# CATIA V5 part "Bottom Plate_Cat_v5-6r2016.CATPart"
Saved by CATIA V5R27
Part number: Bottom Plate
Bounding box of the stored display mesh (mm): x -125 to 125, y 0 to 150, z 0 to 30
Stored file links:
  E:\_Deepak\2017_Deepak\CATIA\Resources\Tutorial Files\Tutorials\c12_catia_v5_6r2015_tut\c12tut2\Bottom Plate_Cat_v5-6r2016.CATPart
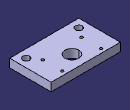
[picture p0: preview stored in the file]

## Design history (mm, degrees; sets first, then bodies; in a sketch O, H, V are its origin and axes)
Body1 (main body)
  Sketch1 on xy-plane, origin (0, 0, 0), H (1, 0, 0), V (0, 1, 0)
    point P1 (-125, 0)
    line L1 (-125, 0) -> (125, 0)
    line L2 (125, 0) -> (125, 150)
    line L3 (125, 150) -> (-125, 150)
    line L4 (-125, 150) -> (-125, 0)
    circle A1 centre (0, 100) radius 25
    point P5 (0, 100)
    circle A2 centre (95, 30) radius 12.5
    point P6 (95, 30)
    circle A3 centre (-95, 30) radius 12.5
    circle A4 centre (-70, 135) radius 5
    point P8 (-70, 135)
    construction line L5 (-25, 100) -> (25, 100)
    point P9 (-25, 100)
    point P10 (25, 100)
    construction line L6 (0, 125) -> (0, 75)
    point P11 (0, 125)
    point P12 (0, 75)
    circle A5 centre (-70, 65) radius 5
    circle A6 centre (70, 135) radius 5
    circle A7 centre (70, 65) radius 5
    length L1 = 250
    length L2 = 150
    radius A1 = 25
    distance P5 L1 = 100
    distance P6 L2 = 30
    distance L1 P6 = 30
    radius A2 = 12.5
    distance P5 P8 V = 35
    distance P5 P8 H = 70
    radius A4 = 5
    distance L1 L5 = 100
    coincidence: P1 H, P5 V, P9 A1, P10 A1, P11 A1, P11 V, P12 A1
    horizontal: L1 H, L3 H, L5 H
    vertical: L2 V, L4 V, L6 V
    symmetry: L4 L2 V, A2 A3 V, A4 A5 L5, A4 A6 L6, A5 A7 L6
  Pad1: profile Sketch1, direction (0, 0, 1), length 30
